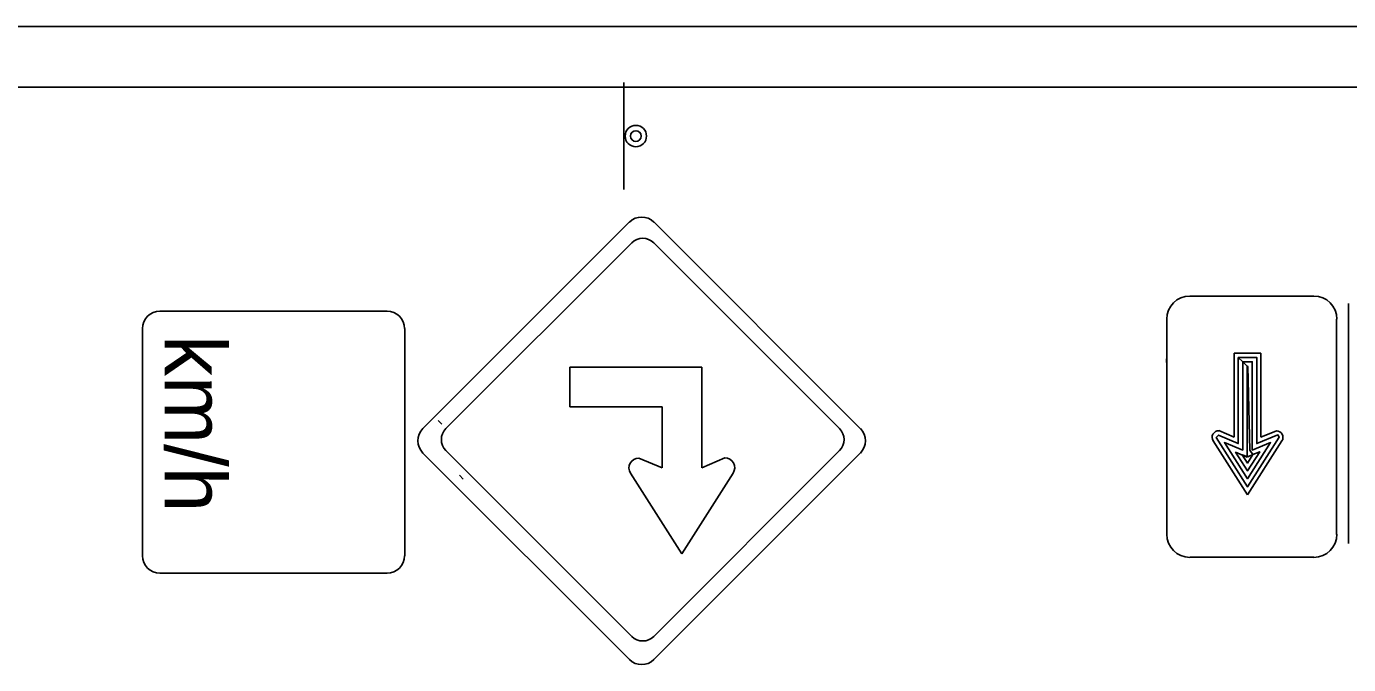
# Model space of a CAD drawing. Extents: x 1806 to 2022, y 110 to 389.
# Drawn here: x 1914.62 to 1940.98, y 266.63 to 279.36 of the extents above; entities that cross this region are included whole.
import ezdxf

# ---------------------------------------------------------------- set-up
doc = ezdxf.new("R2010")
doc.units = 0
for name, color, linetype in [('Level 10', 7, 'Continuous'), ('Level 2', 7, 'Continuous'), ('Level 44', 7, 'Continuous')]:
    doc.layers.add(name, color=color, linetype=linetype)

msp = doc.modelspace()

# ---------------------------------------------------------------- linework, layer by layer
at = {"layer": 'Level 10'}
for p, q in [((1895.86, 279.357), (1957.331, 279.357)), ((1895.86, 278.148), (1957.331, 278.148))]:
    msp.add_line(p, q, dxfattribs=at)
at = {"layer": 'Level 2'}
for p, q in [((1940.98, 273.832), (1940.98, 269.047)), ((1922.905, 271.425), (1922.827, 271.503)), ((1923.33, 270.332), (1923.252, 270.41))]:
    msp.add_line(p, q, dxfattribs=at)
at = {"layer": 'Level 44'}
for p, q in [((1926.532, 278.242), (1926.532, 276.108)), ((1926.642, 275.459), (1922.524, 271.338)), ((1926.642, 275.455), (1926.642, 275.459)), ((1931.244, 271.338), (1927.13, 275.459)), ((1922.982, 271.338), (1926.687, 275.046)), ((1927.127, 275.046), (1930.83, 271.338)), ((1937.82, 273.977), (1940.285, 273.977)), ((1917.281, 273.683), (1917.282, 273.683)), ((1917.282, 273.683), (1921.812, 273.683)), ((1937.355, 269.23), (1937.355, 273.521)), ((1940.742, 273.521), (1940.742, 269.23)), ((1916.933, 268.805), (1916.933, 273.333)), ((1922.161, 273.333), (1922.161, 268.805)), ((1938.701, 272.844), (1938.701, 271.171)), ((1939.234, 272.844), (1938.701, 272.844)), ((1939.234, 271.167), (1939.234, 272.844)), ((1925.451, 272.562), (1928.086, 272.562)), ((1925.451, 271.771), (1925.451, 272.562)), ((1928.086, 272.562), (1928.086, 270.557)), ((1927.295, 271.771), (1925.451, 271.771)), ((1927.295, 270.554), (1927.295, 271.771)), ((1938.701, 271.167), (1938.393, 271.299)), ((1939.541, 271.295), (1939.234, 271.167)), ((1938.282, 271.094), (1938.965, 270.019)), ((1938.965, 270.019), (1939.652, 271.094)), ((1922.524, 270.852), (1926.642, 266.738)), ((1926.687, 267.197), (1922.982, 270.9)), ((1926.832, 270.752), (1927.295, 270.554)), ((1930.83, 270.9), (1927.127, 267.197)), ((1927.13, 266.738), (1931.244, 270.852)), ((1928.086, 270.557), (1928.544, 270.758)), ((1928.711, 270.453), (1927.686, 268.845)), ((1927.686, 268.845), (1926.664, 270.45)), ((1940.285, 268.778), (1937.82, 268.778)), ((1921.812, 268.455), (1917.282, 268.455))]:
    msp.add_line(p, q, dxfattribs=at)
for points in [[(1937.351, 272.727), (1937.351, 272.655)], [(1938.782, 272.754), (1938.782, 271.039), (1938.385, 271.209), (1938.342, 271.163), (1938.965, 270.177), (1939.597, 271.167), (1939.571, 271.214), (1939.149, 271.039), (1939.149, 272.758), (1938.782, 272.754), (1938.871, 272.673), (1938.871, 270.911), (1938.504, 271.06), (1938.965, 270.339), (1939.426, 271.06), (1939.059, 270.911), (1939.059, 272.673), (1938.871, 272.673), (1938.957, 272.583), (1938.957, 270.77), (1938.726, 270.868), (1938.965, 270.497), (1939.208, 270.877), (1939.072, 270.821), (1938.965, 270.651), (1938.858, 270.813), (1938.969, 270.779), (1939.072, 270.821), (1939.012, 270.907), (1938.969, 272.579), (1938.957, 272.583)], [(1938.782, 272.754), (1938.782, 271.039)]]:
    msp.add_lwpolyline(points, dxfattribs=at)
for radius in [0.213, 0.107]:
    msp.add_circle((1926.77, 277.171), radius, dxfattribs=at)
for centre, radius, start, end in [((1926.886, 275.212), 0.345, 45, 135), ((1926.907, 274.825), 0.31, 45, 135), ((1937.817, 273.52), 0.462, 90, 180), ((1940.286, 273.52), 0.462, 0, 90), ((1917.281, 273.333), 0.349, 90, 180), ((1921.81, 273.333), 0.349, 360, 90), ((1922.77, 271.096), 0.345, 135, 225), ((1923.202, 271.12), 0.31, 135, 225), ((1930.611, 271.12), 0.31, 315, 45), ((1931.002, 271.096), 0.345, 315, 45), ((1938.392, 271.165), 0.132, 89.8942, 212.4962), ((1939.54, 271.163), 0.132, 327.5015, 89.8949), ((1926.831, 270.555), 0.198, 90.1051, 212.4986), ((1928.544, 270.559), 0.198, 327.5038, 90.1058), ((1937.817, 269.234), 0.462, 180, 270), ((1940.286, 269.234), 0.462, 270, 360), ((1917.281, 268.804), 0.349, 180, 270), ((1921.81, 268.804), 0.349, 270, 360), ((1926.907, 267.415), 0.31, 225, 315), ((1926.886, 266.979), 0.345, 225, 315)]:
    msp.add_arc(centre, radius, start, end, dxfattribs=at)

# ---------------------------------------------------------------- texts
msp.add_text('km/h', height=1.218, rotation=270, dxfattribs=at).set_placement((1917.375, 273.203))
msp.add_text('km/h', height=1.218, rotation=270, dxfattribs=at).set_placement((1917.375, 273.203))

doc.saveas('drawing.dxf')
